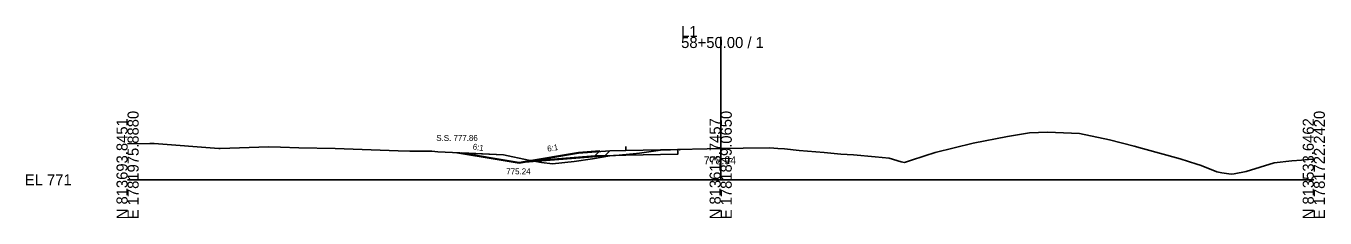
# Model space of a CAD drawing. Extents: x 5574 to 10203, y -10 to 9546.
# Drawn here: x 6574.3 to 6902.8, y 5490.3 to 5539 of the extents above; entities that cross this region are included whole.
import ezdxf

# ---------------------------------------------------------------- set-up
doc = ezdxf.new("R2010")
doc.units = 0
for name, color, linetype in [('Exist Cross Section Cell', 7, 'Continuous'), ('Exist XS Center Line Elevation Label', 7, 'Continuous'), ('Exist XS Ground Line', 7, 'Continuous'), ('Prop XS Ditch Slope Text', 7, 'Continuous'), ('Prop XS Ditch Standard Text', 7, 'Continuous'), ('Prop XS Dump Level', 7, 'Continuous'), ('Prop XS Earthwork Shape', 7, 'Continuous'), ('Prop XS EOT Tick Mark', 7, 'Continuous'), ('Prop XS Finish Grade', 7, 'Continuous'), ('Prop XS Finish Grade Earthwork', 7, 'Continuous'), ('Prop XS Finish Grade Paved Shoulder', 7, 'Continuous'), ('Prop XS Finish Grade Pavement', 7, 'Continuous'), ('Prop XS Hydro Typical Ditch Data', 7, 'Continuous'), ('Prop XS Pvmt Edge Slope', 7, 'Continuous'), ('Prop XS Side Slope Text', 7, 'Continuous'), ('Prop XS SS Elevation Text', 7, 'Continuous'), ('Prop XS Subgrade Earthwork', 7, 'Continuous'), ('Scratch_Level_3', 7, 'Continuous'), ('Scratch_Level_6', 7, 'Continuous')]:
    doc.layers.add(name, color=color, linetype=linetype)

msp = doc.modelspace()

# ---------------------------------------------------------------- linework, layer by layer
at = {"layer": 'Exist Cross Section Cell'}
for p, q in [((6750, 5500), (6750, 5536.2)), ((6600, 5500), (6750, 5500)), ((6750, 5500), (6900, 5500))]:
    msp.add_line(p, q, dxfattribs=at)
at = {"layer": 'Exist XS Ground Line'}
for p, q in [((6813.84, 5509.25), (6822.53, 5511)), ((6822.53, 5511), (6828.12, 5511.92)), ((6828.12, 5511.92), (6832.63, 5512.07)), ((6832.63, 5512.07), (6840.73, 5511.76)), ((6840.73, 5511.76), (6848.34, 5510.12)), ((6848.34, 5510.12), (6854.58, 5508.57)), ((6600, 5509.15), (6605.61, 5509.17)), ((6605.61, 5509.17), (6606.39, 5509.18)), ((6606.39, 5509.18), (6606.71, 5509.17)), ((6606.71, 5509.17), (6623.06, 5507.98)), ((6623.06, 5507.98), (6623.44, 5507.97)), ((6623.44, 5507.97), (6635.67, 5508.38)), ((6635.67, 5508.38), (6638.68, 5508.26)), ((6638.68, 5508.26), (6643.28, 5508.14)), ((6643.28, 5508.14), (6652.46, 5507.95)), ((6652.46, 5507.95), (6668.43, 5507.38)), ((6668.43, 5507.38), (6671.36, 5507.3)), ((6671.36, 5507.3), (6676.97, 5507.25)), ((6676.97, 5507.25), (6678.44, 5507.06)), ((6678.44, 5507.06), (6695.04, 5506.36)), ((6695.04, 5506.36), (6701.42, 5504.94)), ((6723.43, 5506.2), (6727.9, 5506.57)), ((6727.9, 5506.57), (6729.48, 5506.77)), ((6729.48, 5506.77), (6734.77, 5507.51)), ((6734.77, 5507.51), (6737.27, 5507.63)), ((6737.27, 5507.63), (6739.12, 5507.72)), ((6739.12, 5507.72), (6746.55, 5507.87)), ((6746.55, 5507.87), (6750, 5507.94)), ((6750, 5507.94), (6751.23, 5507.96)), ((6751.23, 5507.96), (6755.69, 5508.01)), ((6755.69, 5508.01), (6762.41, 5508.07)), ((6762.41, 5508.07), (6764.46, 5507.97)), ((6764.46, 5507.97), (6766.11, 5507.88)), ((6766.11, 5507.88), (6769.85, 5507.47)), ((6769.85, 5507.47), (6776.21, 5506.91)), ((6776.21, 5506.91), (6780.35, 5506.49)), ((6780.35, 5506.49), (6783.57, 5506.32)), ((6783.57, 5506.32), (6789.06, 5505.82)), ((6801.62, 5506.1), (6804.26, 5506.92)), ((6804.26, 5506.92), (6813.84, 5509.25)), ((6854.58, 5508.57), (6856.64, 5507.96)), ((6856.64, 5507.96), (6866.19, 5505.35)), ((6701.42, 5504.94), (6704.69, 5504.43)), ((6704.69, 5504.43), (6707.43, 5504.05)), ((6707.43, 5504.05), (6712.98, 5504.63)), ((6712.98, 5504.63), (6717.58, 5505.3)), ((6717.58, 5505.3), (6721.93, 5506.04)), ((6721.93, 5506.04), (6723.43, 5506.2)), ((6789.06, 5505.82), (6792.58, 5505.45)), ((6792.58, 5505.45), (6795.66, 5504.53)), ((6795.66, 5504.53), (6796.52, 5504.37)), ((6796.52, 5504.37), (6798.01, 5504.86)), ((6798.01, 5504.86), (6801.62, 5506.1)), ((6866.19, 5505.35), (6870.41, 5503.97)), ((6870.41, 5503.97), (6871.27, 5503.7)), ((6871.27, 5503.7), (6874.07, 5502.61)), ((6882.93, 5502.14), (6890, 5504.34)), ((6890, 5504.34), (6894.48, 5504.81)), ((6894.48, 5504.81), (6896.85, 5505.02)), ((6896.85, 5505.02), (6898.46, 5505.15)), ((6898.46, 5505.15), (6900, 5505.26)), ((6874.07, 5502.61), (6875.52, 5502)), ((6875.52, 5502), (6876.72, 5501.76)), ((6876.72, 5501.76), (6878.53, 5501.49)), ((6878.53, 5501.49), (6879.21, 5501.45)), ((6879.21, 5501.45), (6879.88, 5501.53)), ((6879.88, 5501.53), (6882.93, 5502.14))]:
    msp.add_line(p, q, dxfattribs=at)
at = {"layer": 'Prop XS Dump Level'}
msp.add_line((6739.16, 5507.72), (6726, 5507.46), dxfattribs=at)
msp.add_line((6739.16, 5507.72), (6726, 5507.46), dxfattribs=at)
at = {"layer": 'Prop XS Earthwork Shape'}
for points in [[(6702.4, 5504.79), (6700.46, 5504.64), (6699, 5504.39), (6693, 5505.39), (6684.54, 5506.8), (6695.04, 5506.36), (6701.42, 5504.94)], [(6739.13, 5506.47), (6739.13, 5507.72), (6737.27, 5507.63), (6734.77, 5507.51), (6729.48, 5506.77), (6727.9, 5506.57), (6723.43, 5506.2), (6722.92, 5506.15), (6726, 5506.21)], [(6712.98, 5504.63), (6717.58, 5505.3), (6721.93, 5506.04), (6722.92, 5506.15), (6719.44, 5506.08), (6718.17, 5506.05), (6714, 5505.72), (6702.4, 5504.79), (6704.69, 5504.43), (6707.43, 5504.05)]]:
    msp.add_lwpolyline(points, close=True, dxfattribs=at)
at = {"layer": 'Prop XS EOT Tick Mark'}
msp.add_line((6726, 5507.46), (6726, 5508.46), dxfattribs=at)
at = {"layer": 'Prop XS Finish Grade'}
for p, q in [((6714, 5506.74), (6700.46, 5504.48)), ((6722, 5507.38), (6714, 5506.74))]:
    msp.add_line(p, q, dxfattribs=at)
at = {"layer": 'Prop XS Finish Grade Earthwork'}
for p, q in [((6693, 5505.24), (6683.3, 5506.86)), ((6699, 5504.24), (6693, 5505.24)), ((6700.46, 5504.48), (6699, 5504.24))]:
    msp.add_line(p, q, dxfattribs=at)
at = {"layer": 'Prop XS Finish Grade Paved Shoulder'}
msp.add_line((6726, 5507.46), (6722, 5507.38), dxfattribs=at)
at = {"layer": 'Prop XS Finish Grade Pavement'}
msp.add_line((6739.13, 5507.72), (6726, 5507.46), dxfattribs=at)
at = {"layer": 'Prop XS Hydro Typical Ditch Data'}
for p, q in [((6693, 5505.24), (6683.3, 5506.86)), ((6714, 5506.74), (6699, 5504.24)), ((6699, 5504.24), (6693, 5505.24))]:
    msp.add_line(p, q, dxfattribs=at)
at = {"layer": 'Prop XS Pvmt Edge Slope'}
msp.add_line((6722, 5507.38), (6720.72, 5506.1), dxfattribs=at)
at = {"layer": 'Prop XS Subgrade Earthwork'}
for p, q in [((6726, 5506.21), (6720.72, 5506.1)), ((6739.13, 5506.47), (6726, 5506.21)), ((6739.13, 5506.47), (6739.13, 5507.72)), ((6716.56, 5505.77), (6700.46, 5504.48)), ((6720.72, 5506.1), (6716.56, 5505.77))]:
    msp.add_line(p, q, dxfattribs=at)
at = {"layer": 'Scratch_Level_3'}
for p, q in [((6714, 5506.89), (6700.46, 5504.64)), ((6719.44, 5507.33), (6714, 5506.89)), ((6718.17, 5506.05), (6719.44, 5507.33)), ((6700.46, 5504.64), (6714, 5505.72)), ((6714, 5505.72), (6718.17, 5506.05))]:
    msp.add_line(p, q, dxfattribs=at)
at = {"layer": 'Scratch_Level_6'}
for points in [[(6734.77, 5507.51), (6737.27, 5507.63), (6739.13, 5507.72), (6739.13, 5506.47), (6726, 5506.21), (6722.92, 5506.15), (6723.43, 5506.2), (6727.9, 5506.57), (6729.48, 5506.77)], [(6702.35, 5504.8), (6703.05, 5504.69), (6700.46, 5504.48)]]:
    msp.add_lwpolyline(points, close=True, dxfattribs=at)

# ---------------------------------------------------------------- texts
at = {"layer": 'Exist Cross Section Cell'}
for s, p in [('58+50.00 / 1', (6740, 5533.4)), ('L1', (6740, 5536.2)), ('EL 771', (6574, 5498.6))]:
    msp.add_text(s, height=2.8, dxfattribs=at).set_placement(p)
for s, p in [('E 1781975.8880', (6602.8, 5490)), ('E 1781849.0650', (6752.8, 5490)), ('E 1781722.2420', (6902.8, 5490)), ('N 813693.8451', (6600, 5490)), ('N 813613.7457', (6750, 5490)), ('N 813533.6462', (6900, 5490))]:
    msp.add_text(s, height=2.8, rotation=90, dxfattribs=at).set_placement(p)
at = {"layer": 'Exist XS Center Line Elevation Label'}
msp.add_text('778.94', height=2, dxfattribs=at).set_placement((6745.72, 5503.94))
at = {"layer": 'Prop XS Ditch Slope Text'}
msp.add_text('6:1', height=1.5, rotation=9.4623, dxfattribs=at).set_placement((6706.25, 5507.12))
at = {"layer": 'Prop XS Ditch Standard Text'}
msp.add_text('775.24', height=1.5, dxfattribs=at).set_placement((6695.78, 5501.39))
at = {"layer": 'Prop XS Dump Level'}
for s, height, p in [('Case4', 0.04, (6714, 5506.85)), ('Eop', 0.3, (6739.13, 5507.42))]:
    msp.add_text(s, height=height, dxfattribs=at).set_placement(p)
at = {"layer": 'Prop XS Side Slope Text'}
msp.add_text('6:1', height=1.5, rotation=350.5377, dxfattribs=at).set_placement((6687.2, 5507.73))
at = {"layer": 'Prop XS SS Elevation Text'}
msp.add_text('S.S. 777.86', height=1.5, dxfattribs=at).set_placement((6678.08, 5509.86))

doc.saveas('drawing.dxf')
